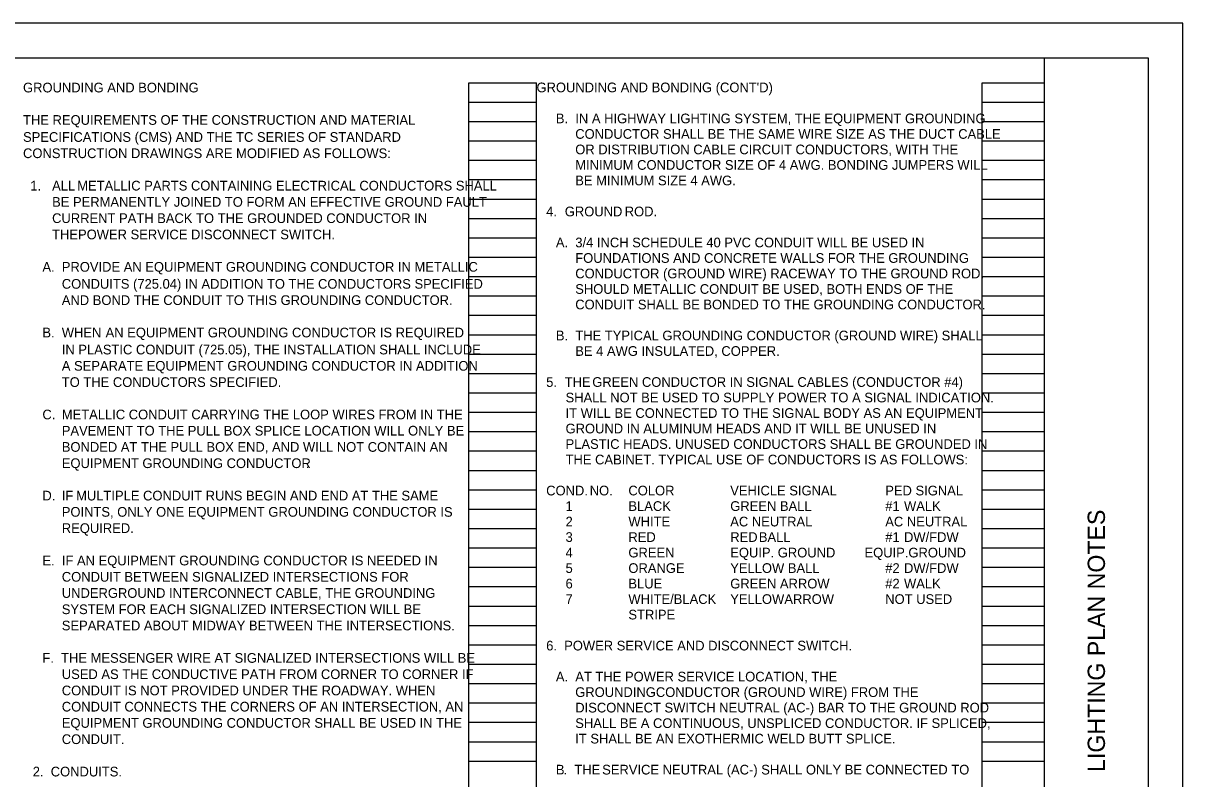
# Model space of a CAD drawing. Extents: x 0 to 34, y 0 to 22.
# Drawn here: x 17.24 to 34, y 11.08 to 22 of the extents above; entities that cross this region are included whole.
import ezdxf

# ---------------------------------------------------------------- set-up
doc = ezdxf.new("R2010")
doc.units = 0
for name, color, linetype in [('SH_Border', 7, 'Continuous'), ('SH_Cut_Line', 7, 'Continuous'), ('SH_Data', 7, 'Continuous'), ('SH_Text', 7, 'Continuous')]:
    doc.layers.add(name, color=color, linetype=linetype)

msp = doc.modelspace()

# ---------------------------------------------------------------- linework, layer by layer
at = {"layer": 'SH_Border'}
msp.add_line((32, 0.5), (32, 21.5), dxfattribs=at)
msp.add_lwpolyline([(1.5, 21.5), (33.5, 21.5), (33.5, 0.5), (1.5, 0.5)], close=True, dxfattribs=at)
at = {"layer": 'SH_Cut_Line'}
msp.add_lwpolyline([(0, 0), (34, 0), (34, 22), (0, 22)], close=True, dxfattribs=at)
at = {"layer": 'SH_Data'}
for p, q in [((23.68, 0.98), (23.68, 21.14)), ((23.68, 21.14), (24.66, 21.14)), ((24.66, 0.98), (24.66, 21.14)), ((31.1, 0.98), (31.1, 21.14)), ((31.1, 21.14), (32, 21.14)), ((32, 0.98), (32, 21.14)), ((23.68, 20.86), (24.66, 20.86)), ((31.1, 20.86), (32, 20.86)), ((23.68, 20.58), (24.66, 20.58)), ((31.1, 20.58), (32, 20.58)), ((23.68, 20.3), (24.66, 20.3)), ((31.1, 20.3), (32, 20.3)), ((23.68, 20.02), (24.66, 20.02)), ((31.1, 20.02), (32, 20.02)), ((23.68, 19.74), (24.66, 19.74)), ((31.1, 19.74), (32, 19.74)), ((23.68, 19.46), (24.66, 19.46)), ((31.1, 19.46), (32, 19.46)), ((23.68, 19.18), (24.66, 19.18)), ((31.1, 19.18), (32, 19.18)), ((23.68, 18.9), (24.66, 18.9)), ((31.1, 18.9), (32, 18.9)), ((23.68, 18.62), (24.66, 18.62)), ((31.1, 18.62), (32, 18.62)), ((23.68, 18.34), (24.66, 18.34)), ((31.1, 18.34), (32, 18.34)), ((23.68, 18.06), (24.66, 18.06)), ((31.1, 18.06), (32, 18.06)), ((23.68, 17.78), (24.66, 17.78)), ((31.1, 17.78), (32, 17.78)), ((23.68, 17.5), (24.66, 17.5)), ((31.1, 17.5), (32, 17.5)), ((23.68, 17.22), (24.66, 17.22)), ((31.1, 17.22), (32, 17.22)), ((23.68, 16.94), (24.66, 16.94)), ((31.1, 16.94), (32, 16.94)), ((23.68, 16.66), (24.66, 16.66)), ((31.1, 16.66), (32, 16.66)), ((23.68, 16.38), (24.66, 16.38)), ((31.1, 16.38), (32, 16.38)), ((23.68, 16.1), (24.66, 16.1)), ((31.1, 16.1), (32, 16.1)), ((23.68, 15.82), (24.66, 15.82)), ((31.1, 15.82), (32, 15.82)), ((23.68, 15.54), (24.66, 15.54)), ((31.1, 15.54), (32, 15.54)), ((23.68, 15.26), (24.66, 15.26)), ((31.1, 15.26), (32, 15.26)), ((23.68, 14.98), (24.66, 14.98)), ((31.1, 14.98), (32, 14.98)), ((23.68, 14.7), (24.66, 14.7)), ((31.1, 14.7), (32, 14.7)), ((23.68, 14.42), (24.66, 14.42)), ((31.1, 14.42), (32, 14.42)), ((23.68, 14.14), (24.66, 14.14)), ((31.1, 14.14), (32, 14.14)), ((23.68, 13.86), (24.66, 13.86)), ((31.1, 13.86), (32, 13.86)), ((23.68, 13.58), (24.66, 13.58)), ((31.1, 13.58), (32, 13.58)), ((23.68, 13.3), (24.66, 13.3)), ((31.1, 13.3), (32, 13.3)), ((23.68, 13.02), (24.66, 13.02)), ((31.1, 13.02), (32, 13.02)), ((23.68, 12.74), (24.66, 12.74)), ((31.1, 12.74), (32, 12.74)), ((23.68, 12.46), (24.66, 12.46)), ((31.1, 12.46), (32, 12.46)), ((23.68, 12.18), (24.66, 12.18)), ((31.1, 12.18), (32, 12.18)), ((23.68, 11.9), (24.66, 11.9)), ((31.1, 11.9), (32, 11.9)), ((23.68, 11.62), (24.66, 11.62)), ((31.1, 11.62), (32, 11.62)), ((23.68, 11.34), (24.66, 11.34)), ((31.1, 11.34), (32, 11.34))]:
    msp.add_line(p, q, dxfattribs=at)

# ---------------------------------------------------------------- texts
msp.add_text('LIGHTING PLAN NOTES', height=0.25, rotation=90, dxfattribs=at).set_placement((32.875, 11.183))
at = {"layer": 'SH_Text'}
for s, p in [('GROUNDING AND BONDING', (17.24, 21)), ("GROUNDING AND BONDING (CONT'D)", (24.66, 21.002)), ('THE REQUIREMENTS OF THE CONSTRUCTION AND MATERIAL ', (17.24, 20.532)), ('B.  IN A HIGHWAY LIGHTING SYSTEM, THE EQUIPMENT GROUNDING ', (24.94, 20.554)), ('CONDUCTOR SHALL BE THE SAME WIRE SIZE AS THE DUCT CABLE ', (25.22, 20.33)), ('SPECIFICATIONS (CMS) AND THE TC SERIES OF STANDARD ', (17.24, 20.286)), ('CONSTRUCTION DRAWINGS ARE MODIFIED AS FOLLOWS:', (17.24, 20.051)), ('OR DISTRIBUTION CABLE CIRCUIT CONDUCTORS, WITH THE ', (25.22, 20.106)), ('MINIMUM CONDUCTOR SIZE OF 4 AWG. BONDING JUMPERS WILL ', (25.22, 19.882)), ('BE MINIMUM SIZE 4 AWG.', (25.22, 19.658)), ('  1.', (17.24, 19.583)), ('ALL ', (17.66, 19.583)), ('METALLIC PARTS CONTAINING ELECTRICAL CONDUCTORS SHALL ', (18.023, 19.583)), ('BE PERMANENTLY JOINED TO FORM AN EFFECTIVE GROUND FAULT ', (17.66, 19.348)), ('4.', (24.8, 19.21)), ('  GROUND ', (24.965, 19.21)), ('ROD.', (25.935, 19.21)), ('CURRENT PATH BACK TO THE GROUNDED CONDUCTOR IN ', (17.66, 19.113)), ('THEPOWER SERVICE DISCONNECT SWITCH.', (17.66, 18.878)), ('A.  3/4 INCH SCHEDULE 40 PVC CONDUIT WILL BE USED IN ', (24.94, 18.762)), ('FOUNDATIONS AND CONCRETE WALLS FOR THE GROUNDING ', (25.22, 18.538)), ('A.', (17.52, 18.41)), ('PROVIDE AN EQUIPMENT GROUNDING CONDUCTOR IN METALLIC ', (17.8, 18.41)), ('CONDUCTOR (GROUND WIRE) RACEWAY TO THE GROUND ROD. ', (25.22, 18.314)), ('CONDUITS (725.04) IN ADDITION TO THE CONDUCTORS SPECIFIED ', (17.8, 18.164)), ('SHOULD METALLIC CONDUIT BE USED, BOTH ENDS OF THE ', (25.22, 18.09)), ('AND BOND THE CONDUIT TO THIS GROUNDING CONDUCTOR.', (17.8, 17.929)), ('CONDUIT SHALL BE BONDED TO THE GROUNDING CONDUCTOR.', (25.22, 17.866)), ('B.', (17.52, 17.461)), ('WHEN ', (17.8, 17.461)), ('AN EQUIPMENT GROUNDING CONDUCTOR IS REQUIRED ', (18.433, 17.461)), ('B.  THE TYPICAL GROUNDING CONDUCTOR (GROUND WIRE) SHALL ', (24.94, 17.418)), ('IN PLASTIC CONDUIT (725.05), THE INSTALLATION SHALL INCLUDE ', (17.8, 17.215)), ('BE 4 AWG INSULATED, COPPER.', (25.22, 17.194)), ('A SEPARATE EQUIPMENT GROUNDING CONDUCTOR IN ADDITION ', (17.8, 16.98)), ('TO THE CONDUCTORS SPECIFIED.', (17.8, 16.745)), ('5.', (24.8, 16.746)), ('  THE ', (24.964, 16.746)), ('GREEN CONDUCTOR IN SIGNAL CABLES (CONDUCTOR #4) ', (25.466, 16.746)), ('SHALL NOT BE USED TO SUPPLY POWER TO A SIGNAL INDICATION. ', (25.08, 16.522)), ('IT WILL BE CONNECTED TO THE SIGNAL BODY AS AN EQUIPMENT ', (25.08, 16.298)), ('C.', (17.52, 16.277)), ('METALLIC CONDUIT CARRYING THE LOOP WIRES FROM IN THE ', (17.8, 16.277)), ('PAVEMENT TO THE PULL BOX SPLICE LOCATION WILL ONLY BE ', (17.8, 16.043)), ('GROUND IN ALUMINUM HEADS AND IT WILL BE UNUSED IN ', (25.08, 16.074)), ('BONDED AT THE PULL BOX END, AND WILL NOT CONTAIN AN ', (17.8, 15.808)), ('PLASTIC HEADS. UNUSED CONDUCTORS SHALL BE GROUNDED IN ', (25.08, 15.85)), ('THE CABINET. TYPICAL USE OF CONDUCTORS IS AS FOLLOWS:', (25.08, 15.626)), ('EQUIPMENT GROUNDING CONDUCTOR', (17.8, 15.573)), ('.', (21.325, 15.573)), ('COND. ', (24.8, 15.178)), ('NO.', (25.429, 15.178)), ('    COLOR', (25.78, 15.178)), ('VEHICLE SIGNAL', (27.46, 15.178)), ('PED SIGNAL', (29.7, 15.178)), ('D.', (17.52, 15.105)), ('IF ', (17.8, 15.105)), ('MULTIPLE CONDUIT RUNS BEGIN AND END AT THE SAME ', (18.007, 15.105)), ('1', (25.08, 14.954)), ('    BLACK', (25.78, 14.954)), ('GREEN BALL', (27.46, 14.954)), ('#1 ', (29.7, 14.954)), ('WALK', (29.971, 14.954)), ('POINTS, ONLY ONE EQUIPMENT GROUNDING CONDUCTOR IS ', (17.8, 14.87)), ('REQUIRED.', (17.8, 14.635)), ('2', (25.08, 14.73)), ('    WHITE', (25.78, 14.73)), ('AC NEUTRAL', (27.46, 14.73)), ('AC NEUTRAL', (29.7, 14.73)), ('3', (25.08, 14.506)), ('    RED', (25.78, 14.506)), ('RED ', (27.46, 14.506)), ('BALL', (27.873, 14.506)), ('#1 ', (29.7, 14.506)), ('DW/FDW', (29.971, 14.506)), ('4', (25.08, 14.282)), ('    GREEN', (25.78, 14.282)), ('EQUIP. GROUND   ', (27.46, 14.282)), ('     EQUIP.GROUND', (29.14, 14.282)), ('E.  IF AN EQUIPMENT GROUNDING CONDUCTOR IS NEEDED IN ', (17.52, 14.167)), ('5', (25.08, 14.058)), ('    ORANGE', (25.78, 14.058)), ('YELLOW BALL', (27.46, 14.058)), ('#2 ', (29.7, 14.058)), ('DW/FDW', (29.971, 14.058)), ('CONDUIT BETWEEN SIGNALIZED INTERSECTIONS FOR ', (17.8, 13.932)), ('6', (25.08, 13.834)), ('    BLUE', (25.78, 13.834)), ('GREEN ARROW', (27.46, 13.834)), ('#2 ', (29.7, 13.834)), ('WALK', (29.971, 13.834)), ('UNDERGROUND INTERCONNECT CABLE, THE GROUNDING ', (17.8, 13.698)), ('7', (25.08, 13.61)), ('    WHITE/BLACK', (25.78, 13.61)), ('YELLOW ', (27.46, 13.61)), ('ARROW', (28.242, 13.61)), ('NOT USED', (29.7, 13.61)), ('SYSTEM FOR EACH SIGNALIZED INTERSECTION WILL BE ', (17.8, 13.463)), ('    STRIPE', (25.78, 13.386)), ('SEPARATED ABOUT MIDWAY BETWEEN THE INTERSECTIONS.', (17.8, 13.228)), ('6.  POWER SERVICE AND DISCONNECT SWITCH.', (24.8, 12.938)), ('F.  THE MESSENGER WIRE AT SIGNALIZED INTERSECTIONS WILL BE ', (17.52, 12.76)), ('USED AS THE CONDUCTIVE PATH FROM CORNER TO CORNER IF ', (17.8, 12.525)), ('A.  AT THE POWER SERVICE LOCATION, THE ', (24.94, 12.49)), ('CONDUIT IS NOT PROVIDED UNDER THE ROADWAY. WHEN ', (17.8, 12.29)), ('GROUNDINGCONDUCTOR (GROUND WIRE) FROM THE ', (25.22, 12.266)), ('CONDUIT CONNECTS THE CORNERS OF AN INTERSECTION, AN ', (17.8, 12.056)), ('DISCONNECT SWITCH NEUTRAL (AC-) BAR TO THE GROUND ROD ', (25.22, 12.042)), ('EQUIPMENT GROUNDING CONDUCTOR SHALL BE USED IN THE ', (17.8, 11.821)), ('SHALL BE A CONTINUOUS, UNSPLICED CONDUCTOR. IF SPLICED, ', (25.22, 11.818)), ('IT SHALL BE AN EXOTHERMIC WELD BUTT SPLICE.', (25.22, 11.594)), ('CONDUIT.', (17.8, 11.586)), ('2.  CONDUITS.', (17.38, 11.118)), ('B', (24.94, 11.146)), ('.  THE ', (25.051, 11.146)), ('SERVICE NEUTRAL (AC-) SHALL ONLY BE CONNECTED TO ', (25.609, 11.146))]:
    msp.add_text(s, height=0.14, dxfattribs=at).set_placement(p)

doc.saveas('drawing.dxf')
